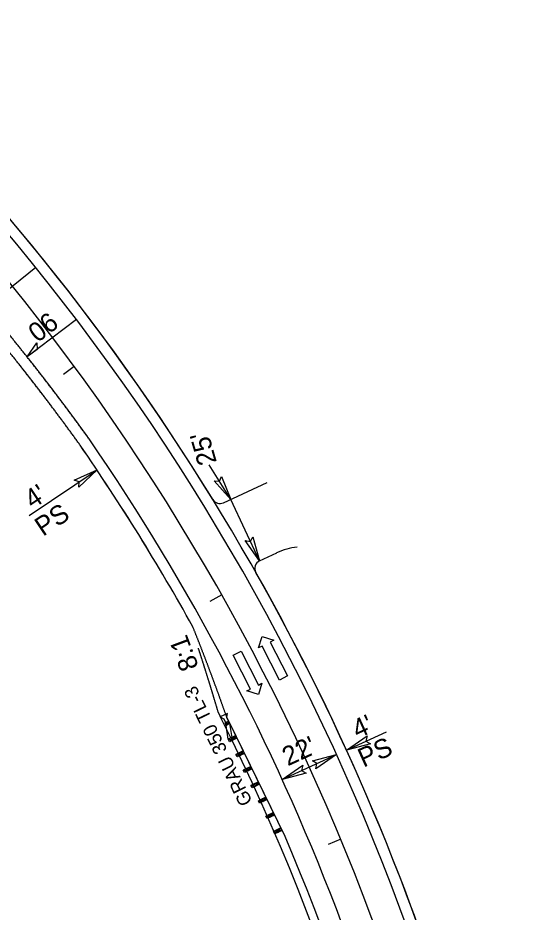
# Model space of a CAD drawing. Extents: x 2167182 to 2168576, y 842635 to 844493.
# Drawn here: x 2167855 to 2168041.5, y 843798.4 to 844127.3 of the extents above; entities that cross this region are included whole.
import ezdxf

# ---------------------------------------------------------------- set-up
doc = ezdxf.new("R2010")
doc.units = 0
for name, color, linetype in [('Prop Dimension', 7, 'Continuous'), ('Prop Dimension Text', 7, 'Continuous'), ('Prop EOT', 7, 'Continuous'), ('Prop Guardrail', 7, 'Continuous'), ('Prop Guardrail Anchor Unit CELL', 7, 'Continuous'), ('Prop Horizontal Alignment', 7, 'Continuous'), ('Prop Horizontal Alignment Tick Small', 7, 'Continuous'), ('Prop Lane Arrow CELL', 7, 'Continuous'), ('Prop Paved Shoulder', 7, 'Continuous'), ('Prop Shade Light', 7, 'Continuous'), ('Prop Superelevation  Arrow CELL', 7, 'Continuous'), ('Prop Superelevation Label', 7, 'Continuous'), ('Prop Terminator CELL', 7, 'Continuous'), ('Scratch_Level_1', 7, 'Continuous')]:
    doc.layers.add(name, color=color, linetype=linetype)

msp = doc.modelspace()

# ---------------------------------------------------------------- linework, layer by layer
at = {"layer": 'Prop Dimension'}
for p, q in [((2167859.12, 843944.35), (2167884.05, 843961.04)), ((2167933.26, 843950.21), (2167925.28, 843962.92)), ((2167943.78, 843927.59), (2167933.26, 843950.21)), ((2167975.78, 843858.03), (2167990.54, 843864.77)), ((2167952.12, 843847.24), (2167972.14, 843856.37))]:
    msp.add_line(p, q, dxfattribs=at)
at = {"layer": 'Prop EOT'}
for radius, end in [(844, 47.10916), (822, 34.57168)]:
    msp.add_arc((2167204.29, 843506.02), radius, 7.27898, end, dxfattribs=at)
msp.add_spline([(2167881.13, 843972.46), (2167880.7, 843973.07), (2167880.26, 843973.67), (2167879.82, 843974.28), (2167879.38, 843974.89), (2167878.94, 843975.5), (2167878.5, 843976.1), (2167878.05, 843976.71), (2167877.61, 843977.32), (2167877.17, 843977.92), (2167876.73, 843978.53), (2167876.28, 843979.13), (2167875.84, 843979.74), (2167875.39, 843980.34), (2167874.95, 843980.94), (2167874.5, 843981.55), (2167874.05, 843982.15), (2167873.61, 843982.75), (2167873.16, 843983.35), (2167872.71, 843983.95), (2167872.26, 843984.56), (2167871.81, 843985.16), (2167871.36, 843985.76), (2167870.91, 843986.36), (2167870.46, 843986.95), (2167870.01, 843987.55), (2167869.56, 843988.15), (2167869.11, 843988.75), (2167868.65, 843989.35), (2167868.2, 843989.94), (2167867.75, 843990.54), (2167867.29, 843991.14), (2167866.84, 843991.73), (2167866.38, 843992.33), (2167865.92, 843992.92), (2167865.47, 843993.52), (2167865.01, 843994.11), (2167864.55, 843994.71), (2167864.09, 843995.3), (2167863.63, 843995.89), (2167863.17, 843996.48), (2167862.71, 843997.08), (2167862.25, 843997.67), (2167861.79, 843998.26), (2167861.33, 843998.85), (2167860.87, 843999.44), (2167860.41, 844000.03), (2167859.94, 844000.62), (2167859.48, 844001.21), (2167859.02, 844001.8), (2167858.55, 844002.38), (2167858.09, 844002.97), (2167857.62, 844003.56), (2167857.15, 844004.15), (2167856.69, 844004.73), (2167856.22, 844005.32), (2167855.75, 844005.9), (2167855.28, 844006.49), (2167854.81, 844007.07), (2167854.34, 844007.66), (2167853.87, 844008.24), (2167853.4, 844008.82), (2167852.93, 844009.41), (2167852.46, 844009.99), (2167851.99, 844010.57), (2167851.52, 844011.15), (2167851.04, 844011.73), (2167850.57, 844012.31), (2167850.09, 844012.89), (2167849.62, 844013.47), (2167849.14, 844014.05), (2167848.67, 844014.63), (2167848.19, 844015.21), (2167847.72, 844015.79), (2167847.24, 844016.37)], degree=3, dxfattribs=at)
at = {"layer": 'Prop Guardrail'}
msp.add_line((2167953.22, 843826.2), (2167931.77, 843870.1), dxfattribs=at)
msp.add_arc((2167204.29, 843506.02), 814.5, 7.27898, 23.14692, dxfattribs=at)
at = {"layer": 'Prop Guardrail Anchor Unit CELL'}
for p, q in [((2167932.07, 843871.5), (2167929.4, 843870.26)), ((2167931.78, 843870.07), (2167932.07, 843871.5)), ((2167929.4, 843870.26), (2167930.68, 843869.55)), ((2167930.68, 843869.55), (2167931.54, 843867.7)), ((2167932.51, 843868.67), (2167931.16, 843868.01)), ((2167931.6, 843867.11), (2167931.16, 843868.01)), ((2167931.16, 843868.01), (2167932.95, 843867.77)), ((2167931.54, 843867.7), (2167932.09, 843867.96)), ((2167932.51, 843868.67), (2167931.6, 843867.11)), ((2167932.65, 843868.21), (2167931.78, 843870.07)), ((2167932.09, 843867.96), (2167932.65, 843868.21)), ((2167953.22, 843826.2), (2167932.73, 843868.22)), ((2167931.6, 843867.11), (2167931.38, 843867.56)), ((2167932.95, 843867.77), (2167931.6, 843867.11)), ((2167932.34, 843862.02), (2167931.6, 843867.11)), ((2167933.72, 843862.69), (2167932.95, 843867.77)), ((2167935.1, 843863.36), (2167932.34, 843862.02)), ((2167932.78, 843861.12), (2167932.34, 843862.02)), ((2167932.34, 843862.02), (2167934.16, 843861.79)), ((2167933.72, 843862.69), (2167932.78, 843861.12)), ((2167935.53, 843862.46), (2167932.78, 843861.12)), ((2167934.16, 843861.79), (2167933.72, 843862.69)), ((2167935.53, 843862.46), (2167933.72, 843862.69)), ((2167934.16, 843861.79), (2167935.1, 843863.36)), ((2167937.86, 843857.7), (2167935.16, 843856.39)), ((2167935.6, 843855.49), (2167935.16, 843856.39)), ((2167935.16, 843856.39), (2167936.95, 843856.14)), ((2167936.51, 843857.04), (2167935.6, 843855.49)), ((2167938.3, 843856.8), (2167935.6, 843855.49)), ((2167936.95, 843856.14), (2167936.51, 843857.04)), ((2167938.3, 843856.8), (2167936.51, 843857.04)), ((2167936.95, 843856.14), (2167937.86, 843857.7)), ((2167940.62, 843852.04), (2167937.8, 843850.66)), ((2167939.65, 843850.45), (2167940.62, 843852.04)), ((2167938.24, 843849.76), (2167937.8, 843850.66)), ((2167937.8, 843850.66), (2167939.65, 843850.45)), ((2167939.21, 843851.35), (2167938.24, 843849.76)), ((2167941.06, 843851.14), (2167938.24, 843849.76)), ((2167939.65, 843850.45), (2167939.21, 843851.35)), ((2167941.06, 843851.14), (2167939.21, 843851.35)), ((2167943.38, 843846.37), (2167940.65, 843845.04)), ((2167941.09, 843844.14), (2167940.65, 843845.04)), ((2167940.65, 843845.04), (2167942.45, 843844.81)), ((2167942.02, 843845.71), (2167941.09, 843844.14)), ((2167943.82, 843845.47), (2167941.09, 843844.14)), ((2167942.45, 843844.81), (2167942.02, 843845.71)), ((2167943.82, 843845.47), (2167942.02, 843845.71)), ((2167942.45, 843844.81), (2167943.38, 843846.37)), ((2167943.82, 843845.47), (2167943.38, 843846.37)), ((2167946.14, 843840.71), (2167943.4, 843839.37)), ((2167943.84, 843838.47), (2167943.4, 843839.37)), ((2167943.4, 843839.37), (2167945.21, 843839.14)), ((2167944.77, 843840.04), (2167943.84, 843838.47)), ((2167946.58, 843839.81), (2167943.84, 843838.47)), ((2167945.21, 843839.14), (2167944.77, 843840.04)), ((2167946.58, 843839.81), (2167944.77, 843840.04)), ((2167945.21, 843839.14), (2167946.14, 843840.71)), ((2167948.9, 843835.04), (2167946.16, 843833.71)), ((2167947.97, 843833.48), (2167948.9, 843835.04)), ((2167946.6, 843832.81), (2167946.16, 843833.71)), ((2167946.16, 843833.71), (2167947.97, 843833.48)), ((2167947.53, 843834.38), (2167946.6, 843832.81)), ((2167949.34, 843834.15), (2167946.6, 843832.81)), ((2167947.97, 843833.48), (2167947.53, 843834.38)), ((2167949.34, 843834.15), (2167947.53, 843834.38)), ((2167951.67, 843829.38), (2167948.97, 843828.07)), ((2167950.32, 843828.72), (2167949.41, 843827.17)), ((2167952.1, 843828.48), (2167949.41, 843827.17)), ((2167951.67, 843829.38), (2167950.32, 843828.72)), ((2167950.76, 843827.82), (2167950.32, 843828.72)), ((2167950.32, 843828.72), (2167952.1, 843828.48)), ((2167950.76, 843827.82), (2167951.67, 843829.38)), ((2167952.1, 843828.48), (2167951.67, 843829.38)), ((2167949.41, 843827.17), (2167948.97, 843828.07)), ((2167948.97, 843828.07), (2167950.76, 843827.82))]:
    msp.add_line(p, q, dxfattribs=at)
at = {"layer": 'Prop Horizontal Alignment'}
msp.add_arc((2167204.29, 843506.02), 833, 7.27898, 47.10916, dxfattribs=at)
at = {"layer": 'Prop Horizontal Alignment Tick Small'}
for p, q in [((2167875.7, 843999.07), (2167871.67, 843996.11)), ((2167929.91, 843915.11), (2167925.56, 843912.66)), ((2167973.68, 843825.27), (2167969.07, 843823.35))]:
    msp.add_line(p, q, dxfattribs=at)
at = {"layer": 'Prop Lane Arrow CELL'}
for p, q in [((2167943.47, 843895.58), (2167944.8, 843899.79)), ((2167944.8, 843899.79), (2167949.08, 843898.43)), ((2167949.08, 843898.43), (2167947.75, 843897.75)), ((2167947.75, 843897.75), (2167954.1, 843885.28)), ((2167934.1, 843892.93), (2167937.04, 843894.43)), ((2167937.04, 843894.43), (2167943.39, 843881.95)), ((2167944.81, 843896.26), (2167943.47, 843895.58)), ((2167951.16, 843883.78), (2167944.81, 843896.26)), ((2167940.45, 843880.46), (2167934.1, 843892.93)), ((2167954.1, 843885.28), (2167951.16, 843883.78)), ((2167943.39, 843881.95), (2167944.72, 843882.63)), ((2167944.72, 843882.63), (2167943.39, 843878.42)), ((2167939.11, 843879.78), (2167940.45, 843880.46)), ((2167943.39, 843878.42), (2167939.11, 843879.78))]:
    msp.add_line(p, q, dxfattribs=at)
at = {"layer": 'Prop Paved Shoulder'}
for p, q in [((2167930.51, 843948.99), (2167946.64, 843956.48)), ((2167943.81, 843927.6), (2167950.12, 843930.53))]:
    msp.add_line(p, q, dxfattribs=at)
for centre, radius, start, end in [((2167204.29, 843506.02), 848, 31.58206, 47.10916), ((2167204.29, 843506.02), 818, 29.06221, 34.57168), ((2167929.25, 843951.71), 3, 211.5821, 294.9246), ((2167960.65, 843907.86), 25, 96.8025, 114.9246), ((2167945.07, 843924.88), 3, 114.9246, 209.4847), ((2167204.29, 843506.02), 848, 16.19989, 29.48474)]:
    msp.add_arc(centre, radius, start, end, dxfattribs=at)
for points in [[(2167877.89, 843970.12), (2167877.45, 843970.73), (2167877.01, 843971.33), (2167876.58, 843971.94), (2167876.14, 843972.54), (2167875.7, 843973.15), (2167875.26, 843973.75), (2167874.82, 843974.35), (2167874.38, 843974.96), (2167873.94, 843975.56), (2167873.5, 843976.16), (2167873.06, 843976.76), (2167872.62, 843977.36), (2167872.17, 843977.97), (2167871.73, 843978.57), (2167871.29, 843979.17), (2167870.84, 843979.77), (2167870.4, 843980.36), (2167869.95, 843980.96), (2167869.51, 843981.56), (2167869.06, 843982.16), (2167868.61, 843982.76), (2167868.16, 843983.35), (2167867.72, 843983.95), (2167867.27, 843984.55), (2167866.82, 843985.14), (2167866.37, 843985.74), (2167865.92, 843986.33), (2167865.47, 843986.93), (2167865.02, 843987.52), (2167864.56, 843988.12), (2167864.11, 843988.71), (2167863.66, 843989.3), (2167863.2, 843989.9), (2167862.75, 843990.49), (2167862.3, 843991.08), (2167861.84, 843991.67), (2167861.39, 843992.26), (2167860.93, 843992.85), (2167860.47, 843993.44), (2167860.01, 843994.03), (2167859.56, 843994.62), (2167859.1, 843995.21), (2167858.64, 843995.8), (2167858.18, 843996.38), (2167857.72, 843996.97), (2167857.26, 843997.56), (2167856.8, 843998.15), (2167856.34, 843998.73), (2167855.88, 843999.32), (2167855.41, 843999.9), (2167854.95, 844000.49), (2167854.49, 844001.07), (2167854.02, 844001.66), (2167853.56, 844002.24), (2167853.09, 844002.82), (2167852.63, 844003.4), (2167852.16, 844003.99), (2167851.69, 844004.57), (2167851.23, 844005.15), (2167850.76, 844005.73), (2167850.29, 844006.31), (2167849.82, 844006.89), (2167849.35, 844007.47), (2167848.88, 844008.05), (2167848.41, 844008.63), (2167847.94, 844009.21), (2167847.47, 844009.78), (2167847, 844010.36), (2167846.53, 844010.94), (2167846.05, 844011.51), (2167845.58, 844012.09), (2167845.11, 844012.67), (2167844.63, 844013.24), (2167844.15, 844013.82)], [(2167931.77, 843870.1), (2167931.61, 843870.55), (2167931.45, 843871), (2167931.29, 843871.46), (2167931.13, 843871.91), (2167930.97, 843872.36), (2167930.81, 843872.81), (2167930.65, 843873.26), (2167930.49, 843873.71), (2167930.33, 843874.17), (2167930.17, 843874.62), (2167930.01, 843875.07), (2167929.85, 843875.52), (2167929.69, 843875.97), (2167929.53, 843876.42), (2167929.36, 843876.87), (2167929.2, 843877.32), (2167929.04, 843877.78), (2167928.88, 843878.23), (2167928.71, 843878.68), (2167928.55, 843879.13), (2167928.38, 843879.58), (2167928.22, 843880.03), (2167928.06, 843880.48), (2167927.89, 843880.93), (2167927.73, 843881.38), (2167927.56, 843881.83), (2167927.39, 843882.28), (2167927.23, 843882.73), (2167927.06, 843883.18), (2167926.9, 843883.63), (2167926.73, 843884.08), (2167926.56, 843884.53), (2167926.39, 843884.98), (2167926.23, 843885.43), (2167926.06, 843885.88), (2167925.89, 843886.33), (2167925.72, 843886.78), (2167925.55, 843887.23), (2167925.38, 843887.68), (2167925.22, 843888.13), (2167925.05, 843888.58), (2167924.88, 843889.03), (2167924.71, 843889.48), (2167924.54, 843889.93), (2167924.36, 843890.38), (2167924.19, 843890.83), (2167924.02, 843891.28), (2167923.85, 843891.73), (2167923.68, 843892.17), (2167923.51, 843892.62), (2167923.34, 843893.07), (2167923.16, 843893.52), (2167922.99, 843893.97), (2167922.82, 843894.42), (2167922.64, 843894.87), (2167922.47, 843895.32), (2167922.3, 843895.76), (2167922.12, 843896.21), (2167921.95, 843896.66), (2167921.77, 843897.11), (2167921.6, 843897.56), (2167921.42, 843898), (2167921.24, 843898.45), (2167921.07, 843898.9), (2167920.89, 843899.35), (2167920.72, 843899.8), (2167920.54, 843900.24), (2167920.36, 843900.69), (2167920.18, 843901.14), (2167920.01, 843901.59), (2167919.83, 843902.03), (2167919.65, 843902.48), (2167919.29, 843903.38)]]:
    msp.add_spline(points, degree=3, dxfattribs=at)
at = {"layer": 'Prop Shade Light'}
msp.add_line((2167953.22, 843826.2), (2167931.77, 843870.1), dxfattribs=at)
for radius, start, end in [(848, 16.19989, 47.10916), (844, 7.27898, 47.10916), (818, 29.06221, 34.56878), (822, 7.27898, 34.57168), (814.5, 7.27898, 23.14692)]:
    msp.add_arc((2167204.29, 843506.02), radius, start, end, dxfattribs=at)
for points in [[(2167866.97, 843984.94), (2167866.92, 843985.01), (2167866.87, 843985.08), (2167866.82, 843985.14), (2167866.67, 843985.34), (2167866.52, 843985.54), (2167866.37, 843985.74), (2167866.22, 843985.94), (2167866.07, 843986.14), (2167865.92, 843986.33), (2167865.77, 843986.53), (2167865.62, 843986.73), (2167865.47, 843986.93), (2167865.32, 843987.13), (2167865.17, 843987.33), (2167865.02, 843987.52), (2167864.86, 843987.72), (2167864.71, 843987.92), (2167864.56, 843988.12), (2167864.41, 843988.31), (2167864.26, 843988.51), (2167864.11, 843988.71), (2167863.96, 843988.91), (2167863.81, 843989.11), (2167863.66, 843989.3), (2167863.51, 843989.5), (2167863.36, 843989.7), (2167863.2, 843989.9), (2167863.05, 843990.09), (2167862.9, 843990.29), (2167862.75, 843990.49), (2167862.6, 843990.68), (2167862.45, 843990.88), (2167862.3, 843991.08), (2167862.14, 843991.28), (2167861.99, 843991.47), (2167861.84, 843991.67), (2167861.69, 843991.87), (2167861.54, 843992.06), (2167861.39, 843992.26), (2167861.23, 843992.46), (2167861.08, 843992.65), (2167860.93, 843992.85), (2167860.78, 843993.05), (2167860.62, 843993.25), (2167860.47, 843993.44), (2167860.32, 843993.64), (2167860.17, 843993.83), (2167860.01, 843994.03), (2167859.86, 843994.23), (2167859.71, 843994.42), (2167859.56, 843994.62), (2167859.4, 843994.82), (2167859.25, 843995.01), (2167859.1, 843995.21), (2167858.95, 843995.4), (2167858.79, 843995.6), (2167858.64, 843995.8), (2167858.49, 843995.99), (2167858.33, 843996.19), (2167858.18, 843996.38), (2167858.03, 843996.58), (2167857.87, 843996.78), (2167857.72, 843996.97), (2167857.57, 843997.17), (2167857.41, 843997.36), (2167857.26, 843997.56), (2167857.11, 843997.75), (2167856.95, 843997.95), (2167856.8, 843998.15), (2167856.65, 843998.34), (2167856.49, 843998.54), (2167856.34, 843998.73), (2167856.18, 843998.93), (2167856.03, 843999.12), (2167855.88, 843999.32), (2167855.83, 843999.38), (2167855.78, 843999.44), (2167855.73, 843999.51)], [(2167858.87, 844001.99), (2167858.92, 844001.92), (2167858.97, 844001.86), (2167859.02, 844001.8), (2167859.17, 844001.6), (2167859.32, 844001.4), (2167859.48, 844001.21), (2167859.63, 844001.01), (2167859.79, 844000.82), (2167859.94, 844000.62), (2167860.1, 844000.42), (2167860.25, 844000.23), (2167860.41, 844000.03), (2167860.56, 843999.83), (2167860.71, 843999.64), (2167860.87, 843999.44), (2167861.02, 843999.24), (2167861.18, 843999.05), (2167861.33, 843998.85), (2167861.49, 843998.65), (2167861.64, 843998.46), (2167861.79, 843998.26), (2167861.95, 843998.06), (2167862.1, 843997.86), (2167862.25, 843997.67), (2167862.41, 843997.47), (2167862.56, 843997.27), (2167862.71, 843997.08), (2167862.87, 843996.88), (2167863.02, 843996.68), (2167863.17, 843996.48), (2167863.33, 843996.29), (2167863.48, 843996.09), (2167863.63, 843995.89), (2167863.79, 843995.69), (2167863.94, 843995.5), (2167864.09, 843995.3), (2167864.25, 843995.1), (2167864.4, 843994.9), (2167864.55, 843994.71), (2167864.7, 843994.51), (2167864.86, 843994.31), (2167865.01, 843994.11), (2167865.16, 843993.91), (2167865.31, 843993.72), (2167865.47, 843993.52), (2167865.62, 843993.32), (2167865.77, 843993.12), (2167865.92, 843992.92), (2167866.08, 843992.73), (2167866.23, 843992.53), (2167866.38, 843992.33), (2167866.53, 843992.13), (2167866.68, 843991.93), (2167866.84, 843991.73), (2167866.99, 843991.53), (2167867.14, 843991.34), (2167867.29, 843991.14), (2167867.44, 843990.94), (2167867.59, 843990.74), (2167867.75, 843990.54), (2167867.9, 843990.34), (2167868.05, 843990.14), (2167868.2, 843989.94), (2167868.35, 843989.75), (2167868.5, 843989.55), (2167868.65, 843989.35), (2167868.8, 843989.15), (2167868.96, 843988.95), (2167869.11, 843988.75), (2167869.26, 843988.55), (2167869.41, 843988.35), (2167869.56, 843988.15), (2167869.71, 843987.95), (2167869.86, 843987.75), (2167870.01, 843987.55), (2167870.06, 843987.48), (2167870.11, 843987.42), (2167870.17, 843987.35)], [(2167870.17, 843987.35), (2167870.26, 843987.22), (2167870.36, 843987.09), (2167870.46, 843986.95), (2167870.61, 843986.75), (2167870.76, 843986.56), (2167870.91, 843986.36), (2167871.06, 843986.16), (2167871.21, 843985.96), (2167871.36, 843985.76), (2167871.51, 843985.56), (2167871.66, 843985.36), (2167871.81, 843985.16), (2167871.96, 843984.96), (2167872.11, 843984.76), (2167872.26, 843984.56), (2167872.41, 843984.35), (2167872.56, 843984.15), (2167872.71, 843983.95), (2167872.86, 843983.75), (2167873.01, 843983.55), (2167873.16, 843983.35), (2167873.31, 843983.15), (2167873.46, 843982.95), (2167873.61, 843982.75), (2167873.76, 843982.55), (2167873.91, 843982.35), (2167874.05, 843982.15), (2167874.2, 843981.95), (2167874.35, 843981.75), (2167874.5, 843981.55), (2167874.65, 843981.35), (2167874.8, 843981.14), (2167874.95, 843980.94), (2167875.1, 843980.74), (2167875.24, 843980.54), (2167875.39, 843980.34), (2167875.54, 843980.14), (2167875.69, 843979.94), (2167875.84, 843979.74), (2167875.99, 843979.53), (2167876.13, 843979.33), (2167876.28, 843979.13), (2167876.43, 843978.93), (2167876.58, 843978.73), (2167876.73, 843978.53), (2167876.87, 843978.33), (2167877.02, 843978.12), (2167877.17, 843977.92), (2167877.32, 843977.72), (2167877.46, 843977.52), (2167877.61, 843977.32), (2167877.76, 843977.11), (2167877.91, 843976.91), (2167878.05, 843976.71), (2167878.2, 843976.51), (2167878.35, 843976.31), (2167878.5, 843976.1), (2167878.64, 843975.9), (2167878.79, 843975.7), (2167878.94, 843975.5), (2167879.08, 843975.3), (2167879.23, 843975.09), (2167879.38, 843974.89), (2167879.52, 843974.69), (2167879.67, 843974.49), (2167879.82, 843974.28), (2167879.96, 843974.08), (2167880.11, 843973.88), (2167880.26, 843973.67), (2167880.4, 843973.47), (2167880.55, 843973.27), (2167880.7, 843973.07), (2167880.84, 843972.86), (2167880.99, 843972.66), (2167881.13, 843972.46)]]:
    msp.add_open_spline(points, degree=3, dxfattribs=at)
msp.add_spline([(2167931.77, 843870.1), (2167931.61, 843870.55), (2167931.45, 843871), (2167931.29, 843871.46), (2167931.13, 843871.91), (2167930.97, 843872.36), (2167930.81, 843872.81), (2167930.65, 843873.26), (2167930.49, 843873.71), (2167930.33, 843874.17), (2167930.17, 843874.62), (2167930.01, 843875.07), (2167929.85, 843875.52), (2167929.69, 843875.97), (2167929.53, 843876.42), (2167929.36, 843876.87), (2167929.2, 843877.32), (2167929.04, 843877.78), (2167928.88, 843878.23), (2167928.71, 843878.68), (2167928.55, 843879.13), (2167928.38, 843879.58), (2167928.22, 843880.03), (2167928.06, 843880.48), (2167927.89, 843880.93), (2167927.73, 843881.38), (2167927.56, 843881.83), (2167927.39, 843882.28), (2167927.23, 843882.73), (2167927.06, 843883.18), (2167926.9, 843883.63), (2167926.73, 843884.08), (2167926.56, 843884.53), (2167926.39, 843884.98), (2167926.23, 843885.43), (2167926.06, 843885.88), (2167925.89, 843886.33), (2167925.72, 843886.78), (2167925.55, 843887.23), (2167925.38, 843887.68), (2167925.22, 843888.13), (2167925.05, 843888.58), (2167924.88, 843889.03), (2167924.71, 843889.48), (2167924.54, 843889.93), (2167924.36, 843890.38), (2167924.19, 843890.83), (2167924.02, 843891.28), (2167923.85, 843891.73), (2167923.68, 843892.17), (2167923.51, 843892.62), (2167923.34, 843893.07), (2167923.16, 843893.52), (2167922.99, 843893.97), (2167922.82, 843894.42), (2167922.64, 843894.87), (2167922.47, 843895.32), (2167922.3, 843895.76), (2167922.12, 843896.21), (2167921.95, 843896.66), (2167921.77, 843897.11), (2167921.6, 843897.56), (2167921.42, 843898), (2167921.24, 843898.45), (2167921.07, 843898.9), (2167920.89, 843899.35), (2167920.72, 843899.8), (2167920.54, 843900.24), (2167920.36, 843900.69), (2167920.18, 843901.14), (2167920.01, 843901.59), (2167919.83, 843902.03), (2167919.65, 843902.48), (2167919.29, 843903.38)], degree=3, dxfattribs=at)
at = {"layer": 'Prop Superelevation  Arrow CELL'}
for p, q in [((2167861.54, 844035.51), (2167843.43, 844020.93)), ((2167876.52, 844016.36), (2167858.38, 844002.6))]:
    msp.add_line(p, q, dxfattribs=at)
msp.add_lwpolyline([(2167858.38, 844002.6), (2167861.95, 844007.82), (2167862.07, 844005.39)], close=True, dxfattribs=at)
at = {"layer": 'Prop Terminator CELL'}
for points in [[(2167875.71, 843957.32), (2167884.05, 843961.04), (2167877.42, 843954.68), (2167877.49, 843956.65)], [(2167929.79, 843958.66), (2167933.26, 843950.21), (2167927.09, 843957.02), (2167929.06, 843956.9)], [(2167941.39, 843936.4), (2167943.78, 843927.59), (2167938.51, 843935.12), (2167940.45, 843934.75)], [(2167984.61, 843860.36), (2167975.78, 843858.03), (2167983.34, 843863.24), (2167982.96, 843861.31)], [(2167963.31, 843854.04), (2167972.14, 843856.37), (2167964.57, 843851.16), (2167964.95, 843853.09)], [(2167960.95, 843849.56), (2167952.12, 843847.24), (2167959.69, 843852.45), (2167959.31, 843850.52)]]:
    msp.add_lwpolyline(points, close=True, dxfattribs=at)
at = {"layer": 'Scratch_Level_1'}
msp.add_line((2167929.98, 843869.2), (2167928.67, 843871.82), dxfattribs=at)
msp.add_arc((2167204.29, 843506.02), 811.5, 7.27898, 26.58604, dxfattribs=at)
msp.add_spline([(2167928.67, 843871.82), (2167928.57, 843872.14), (2167928.48, 843872.46), (2167928.39, 843872.78), (2167928.29, 843873.1), (2167928.2, 843873.42), (2167928.1, 843873.74), (2167928.01, 843874.06), (2167927.91, 843874.38), (2167927.82, 843874.71), (2167927.72, 843875.03), (2167927.62, 843875.35), (2167927.53, 843875.67), (2167927.43, 843875.99), (2167927.34, 843876.31), (2167927.24, 843876.63), (2167927.14, 843876.95), (2167927.05, 843877.27), (2167926.95, 843877.59), (2167926.86, 843877.92), (2167926.76, 843878.24), (2167926.66, 843878.56), (2167926.56, 843878.88), (2167926.47, 843879.2), (2167926.37, 843879.52), (2167926.27, 843879.84), (2167926.17, 843880.16), (2167926.08, 843880.48), (2167925.98, 843880.8), (2167925.88, 843881.12), (2167925.78, 843881.44), (2167925.68, 843881.76), (2167925.59, 843882.09), (2167925.49, 843882.41), (2167925.39, 843882.73), (2167925.29, 843883.05), (2167925.19, 843883.37), (2167925.09, 843883.69), (2167924.99, 843884.01), (2167924.89, 843884.33), (2167924.79, 843884.65), (2167924.69, 843884.97), (2167924.59, 843885.29), (2167924.49, 843885.61), (2167924.39, 843885.93), (2167924.29, 843886.25), (2167924.19, 843886.57), (2167924.09, 843886.89), (2167923.99, 843887.21), (2167923.89, 843887.53), (2167923.79, 843887.85), (2167923.69, 843888.17), (2167923.59, 843888.49), (2167923.48, 843888.81), (2167923.38, 843889.13), (2167923.28, 843889.46), (2167923.18, 843889.78), (2167923.08, 843890.1), (2167922.97, 843890.42), (2167922.87, 843890.74), (2167922.77, 843891.06), (2167922.67, 843891.38), (2167922.56, 843891.7), (2167922.46, 843892.02), (2167922.36, 843892.34), (2167922.25, 843892.66), (2167922.15, 843892.98), (2167922.05, 843893.3), (2167921.94, 843893.62), (2167921.84, 843893.94), (2167921.74, 843894.26), (2167921.63, 843894.58), (2167921.53, 843894.9), (2167921.32, 843895.54)], degree=3, dxfattribs=at)

# ---------------------------------------------------------------- texts
at = {"layer": 'Prop Dimension Text'}
for s, rotation, p in [("25'", 106.1042, (2167928.16, 843963.94)), ("4'", 33.797, (2167860.37, 843946.51)), ('PS', 33.797, (2167864.2, 843936.44)), ('8:1', 110.5512, (2167921.54, 843888.69)), ("4'", 24.5257, (2167979.88, 843862.09)), ("22'", 24.5257, (2167954.18, 843852.02)), ('PS', 24.5257, (2167982.03, 843851.53))]:
    msp.add_text(s, height=7, rotation=rotation, dxfattribs=at).set_placement(p)
at = {"layer": 'Prop Guardrail Anchor Unit CELL'}
msp.add_text('GRAU 350 TL-3', height=5, rotation=116.0386, dxfattribs=at).set_placement((2167941.35, 843839.01))
at = {"layer": 'Prop Superelevation Label'}
msp.add_text('06', height=7, rotation=37.2047, dxfattribs=at).set_placement((2167862.18, 844007.67))

doc.saveas('drawing.dxf')
